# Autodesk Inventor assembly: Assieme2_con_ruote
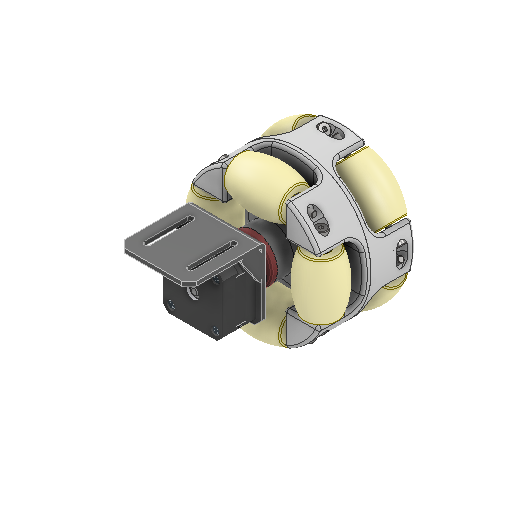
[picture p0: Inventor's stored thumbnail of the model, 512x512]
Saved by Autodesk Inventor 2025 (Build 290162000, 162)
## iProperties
Created: 2025-05
Part Number: Assieme2_con_ruote
Document SubType Name: Assembly
Designer: R5800u
Author: R5800u
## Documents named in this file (10)
- C:\Users\R5800u\Desktop\mecanum6\Assieme2_con_ruote.iam
- C:\Users\R5800u\Desktop\mecanum6\Assieme1.iam
- C:\Users\R5800u\Desktop\mecanum6\rullo.ipt
- C:\Users\R5800u\Desktop\mecanum6\blocco_albero_ruota.ipt
- C:\Users\R5800u\Desktop\mecanum6\vite2.ipt
- C:\Users\R5800u\Desktop\mecanum6\vite3.ipt
- C:\Users\R5800u\Desktop\mecanum6\nema17_pancake.iam
- C:\Users\R5800u\Desktop\mecanum6\NEMA 17 A-Body.ipt
- C:\Users\R5800u\Documents\Inventor\Content Center Files\R2025\it-IT\BS 290 SKF(30)\BS 290 SKF - SKF 604.ipt
- C:\Users\R5800u\Documents\Inventor\Content Center Files\R2025\it-IT\AS 1237 (2.1)\AS 1237 - 4.ipt
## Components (27 placed, 9 different names)
1. Assieme1:1 [sub-assembly] — Coincidente:1, Coincidente:2, Rotazionale:1, Coincidente:3, Coincidente:4, Coincidente:5, Rotazionale:3, Rotazionale:4
2. blocco_albero_ruota:1 — Rotazionale:1, Rotazionale:2, Coincidente:6, Coincidente:7
3. nema17_pancake:1 [sub-assembly] — Angolo:1, Coincidente:6, Coincidente:7, Rotazionale:5
4. NEMA 17 A-Body:2 — Rotazionale:5
5. BS 290 SKF 604:1 — Coincidente:9
6. BS 290 SKF 604:2 — Rotazionale:6, Coincidente:11
7. AS 1237 (2.1) 4:1 — Coincidente:9
8. AS 1237 (2.1) 4:2 — Coincidente:11
9. rullo:1 — Coincidente:1, Coincidente:2, Rotazionale:6
10. rullo:2
11. rullo:3
12. rullo:4
13. rullo:5 — Coincidente:3, Coincidente:4
14. rullo:6
15. rullo:7
16. rullo:8
17. vite2:1 — Rotazionale:2, Coincidente:5
18. vite2:2
19. vite2:3
20. vite3:1 — Rotazionale:3
21. vite3:2
22. vite3:3
23. vite3:4
24. vite3:5 — Rotazionale:4
25. vite3:6
26. vite3:7
27. vite3:8
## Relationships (16: Mate 9, RevoluteJoint 6, Angle 1)
- Coincidente:1 [Mate]: Assieme1:1 ↔ rullo:1
- Coincidente:2 [Mate]: Assieme1:1 ↔ rullo:1
- Rotazionale:1 [RevoluteJoint]: Assieme1:1 ↔ blocco_albero_ruota:1
- Coincidente:3 [Mate]: Assieme1:1 ↔ rullo:5
- Coincidente:4 [Mate]: Assieme1:1 ↔ rullo:5
- Rotazionale:2 [RevoluteJoint]: blocco_albero_ruota:1 ↔ vite2:1
- Coincidente:5 [Mate]: Assieme1:1 ↔ vite2:1
- Rotazionale:3 [RevoluteJoint]: Assieme1:1 ↔ vite3:1
- Rotazionale:4 [RevoluteJoint]: Assieme1:1 ↔ vite3:5
- Angolo:1 [Angle]: nema17_pancake:1
- Coincidente:6 [Mate]: blocco_albero_ruota:1 ↔ nema17_pancake:1
- Coincidente:7 [Mate]: blocco_albero_ruota:1 ↔ nema17_pancake:1
- Rotazionale:5 [RevoluteJoint]: nema17_pancake:1 ↔ NEMA 17 A-Body:2
- Rotazionale:6 [RevoluteJoint]: BS 290 SKF 604:2 ↔ rullo:1
- Coincidente:9 [Mate]: BS 290 SKF 604:1 ↔ AS 1237 (2.1) 4:1
- Coincidente:11 [Mate]: BS 290 SKF 604:2 ↔ AS 1237 (2.1) 4:2
